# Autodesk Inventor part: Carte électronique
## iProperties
Created: 2010-07
Part Number: Carte électronique
Document SubType Name: Modeling
Designer: eric
Density: 1 g/cm^3
Author: eric
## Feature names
1. Base1
